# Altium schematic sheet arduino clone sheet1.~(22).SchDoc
size A; SheetNumber: 1; SheetTotal: 2
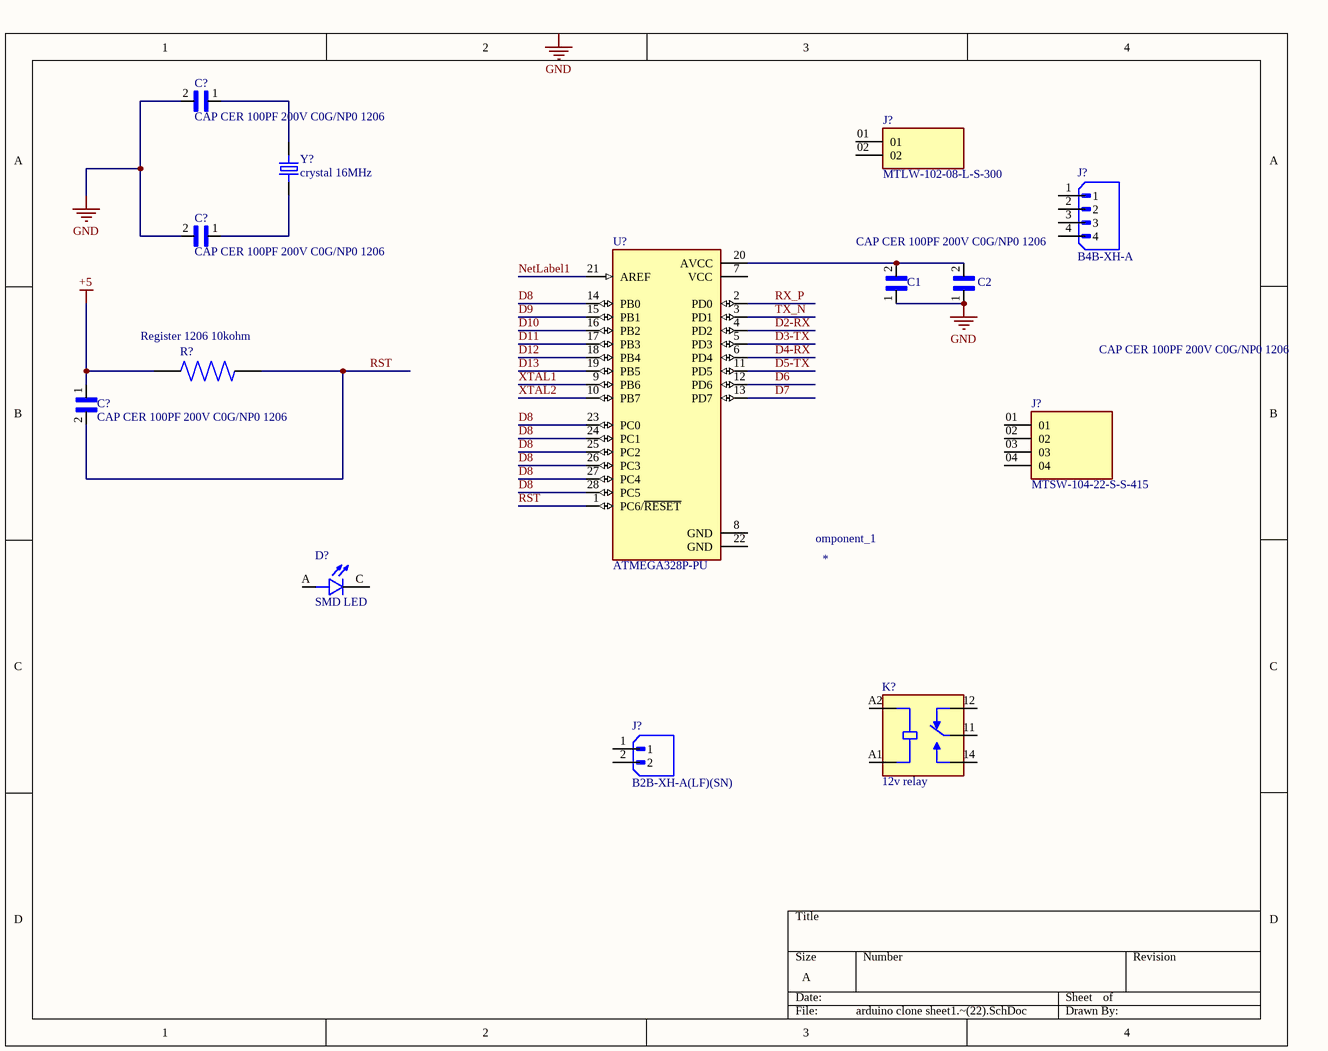
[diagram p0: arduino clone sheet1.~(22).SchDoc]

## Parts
(Parts that share a designator on the sheet are numbered #1, #2 ... from top to bottom, then left to right.)
*  omponent_1
C1  CAP CER 100PF 200V C0G/NP0 1206  [CAPC3216X88N]
C2  CAP CER 100PF 200V C0G/NP0 1206  [CAPC3216X88N]
C?#1  CAP CER 100PF 200V C0G/NP0 1206  [CAPC3216X88N]
C?#2  CAP CER 100PF 200V C0G/NP0 1206  [CAPC3216X88N]
C?#3  CAP CER 100PF 200V C0G/NP0 1206  [CAPC3216X88N]
D?  SMD LED  [LED_BR1102W-TR]
J?#1  MTLW-102-08-L-S-300  [SAMTEC_MTLW-102-08-L-S-300]
J?#2  B4B-XH-A  [JST_B4B-XH-A]
J?#3  MTSW-104-22-S-S-415  [SAMTEC_MTSW-104-22-S-S-415]
J?#4  B2B-XH-A(LF)(SN)  [JST_B2B-XH-A(LF)(SN)]
K?  12v relay  [RELAY_833H-1C-S-12VDC]
R?  Register 1206 10kohm  [RESC3015X65N]
U?  ATMEGA328P-PU  [DIP794W46P254L2967H457Q28B]
Y?  crystal 16MHz  [XTAL_ECS-160-20-5PX-TR]

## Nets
+5: C?#3.1 R?.1
GND: C1.1 C2.1 C?#1.2 C?#2.2
D2-RX: U?.4(PD2)
D3-TX: U?.5(PD3)
D4-RX: U?.6(PD4)
D5-TX: U?.11(PD5)
D6: U?.12(PD6)
D7: U?.13(PD7)
D8: U?.14(PB0) U?.23(PC0) U?.24(PC1) U?.25(PC2) U?.26(PC3) U?.27(PC4) U?.28(PC5)
D9: U?.15(PB1)
D10: U?.16(PB2)
D11: U?.17(PB3)
D12: U?.18(PB4)
D13: U?.19(PB5)
NetLabel1: U?.21(AREF)
RST: C?#3.2 R?.2 U?.1(PC6/~{RESET})
RX_P: U?.2(PD0)
TX_N: U?.3(PD1)
XTAL1: U?.9(PB6)
XTAL2: U?.10(PB7)
NetC1_2: C1.2 C2.2 U?.20(AVCC)
NetC?#1_1: C?#1.1 Y?.2
NetC?#2_1: C?#2.1 Y?.1

Not connected (* = marked no-connect by the designer): D? A C; J?#1 01 02; J?#2 1 2 3 4; J?#3 01 02 03 04; J?#4 1 2; K? 11(COM) 12(NC) 14(NO) A1(COIL2) A2(COIL1); U? 7(VCC) 8(GND) 22(GND)

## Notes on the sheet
- Labels drawn without touching a wire or pin: GND

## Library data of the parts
* = Component_1
C1 C2 C?#1-C?#3 = C1206C101J2GACTU
D? = BR1102W-TR: LED Uni-Color Red 660nm 2-Pin SMD T/R
J?#2 = B4B-XH-A: Connector Header Through Hole 4 position 0.098 (2.50mm); MF: JST Sales
J?#4 = B2B-XH-A(LF)(SN): Connector Header Through Hole 2 position 0.098 (2.50mm); MF: JST Sales
K? = 833H-1C-S-12VDC: 833H Series 10 A SPDT 12 VDC Through Hole Miniature Sugar Cube Power Relay; MF: Song Chuan
R? = Register 1206 10kohm: MP: RNCF1206BKY10K0
U? = ATMEGA328P-PU: ATmega Series 20 MHz 32 KB Flash 2 KB SRAM 8-Bit Microcontroller - DIP-28
Y? = ECS-160-20-5PX-TR: 16 MHz Â±30ppm Crystal 20pF 40 Ohms HC-49/US; MF: ECS Inc.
